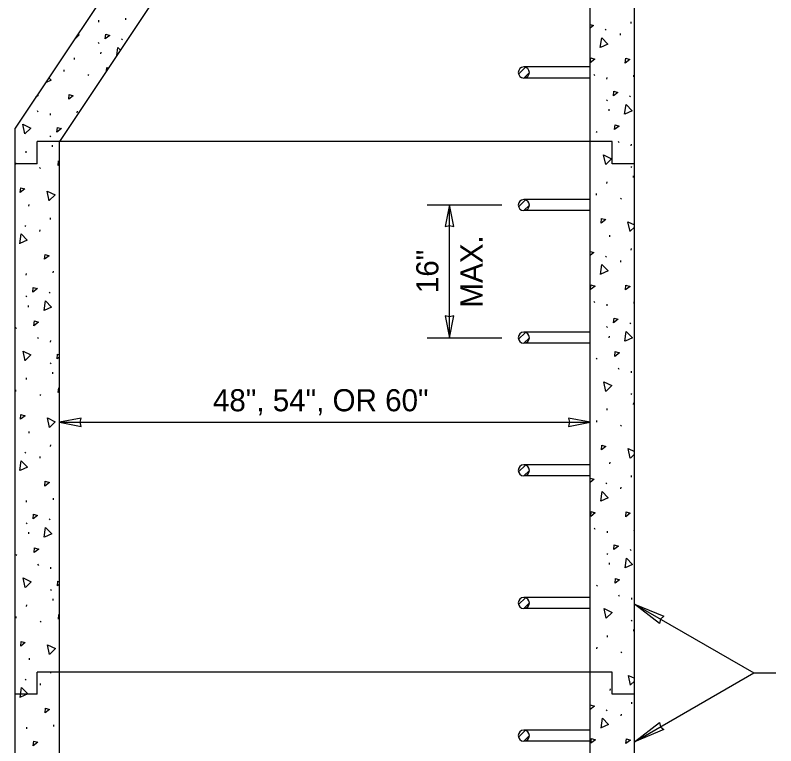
# Model space of a CAD drawing. Extents: x 99862 to 104211, y 98939 to 102076.
# Drawn here: x 100813 to 101364, y 101014 to 101543 of the extents above; entities that cross this region are included whole.
import ezdxf

# ---------------------------------------------------------------- set-up
doc = ezdxf.new("R2010")
doc.units = 0
for name, color, linetype in [('Level 15', 7, 'Continuous'), ('Level 17', 7, 'Continuous'), ('Level 18', 7, 'Continuous'), ('Level 19', 7, 'Continuous'), ('Level 20', 7, 'Continuous')]:
    doc.layers.add(name, color=color, linetype=linetype)

msp = doc.modelspace()

# ---------------------------------------------------------------- linework, layer by layer
at = {"layer": 'Level 15'}
for p, q in [((101111.39, 101406.06), (101165.22, 101406.06)), ((101127.39, 101309.84), (101127.39, 101406.06)), ((101111.39, 101309.84), (101165.22, 101309.84)), ((100845.22, 101248.56), (101229.22, 101248.56)), ((101261.22, 101116.96), (101347.53, 101067.13)), ((101261.22, 101017.3), (101347.53, 101067.13)), ((101347.53, 101067.13), (101363.53, 101067.13))]:
    msp.add_line(p, q, dxfattribs=at)
for points in [[(101127.39, 101406.06), (101124.3, 101390.33), (101127.39, 101391.06), (101130.47, 101390.33)], [(101127.39, 101309.84), (101130.47, 101325.56), (101127.39, 101324.84), (101124.3, 101325.56)], [(100845.22, 101248.56), (100860.94, 101245.48), (100860.21, 101248.56), (100860.94, 101251.64)], [(101229.22, 101248.56), (101213.49, 101251.64), (101214.22, 101248.56), (101213.49, 101245.48)], [(101261.22, 101116.96), (101282.48, 101108.13), (101280.07, 101106.07), (101279.5, 101102.96)], [(101261.22, 101017.3), (101279.5, 101031.3), (101280.07, 101028.18), (101282.48, 101026.13)]]:
    msp.add_lwpolyline(points, close=True, dxfattribs=at)
at = {"layer": 'Level 17'}
for p, q in [((101229.22, 100299.79), (101229.22, 101853.53)), ((101261.22, 100251.79), (101261.22, 101853.53)), ((101005.22, 101749.47), (100813.22, 101461.47)), ((101037.22, 101739.79), (100845.22, 101451.79)), ((100813.22, 100251.79), (100813.22, 101461.47)), ((100829.22, 101435.79), (100829.22, 101451.79)), ((100845.22, 101451.79), (100829.22, 101451.79)), ((101229.22, 101451.79), (100845.22, 101451.79)), ((100845.22, 100299.79), (100845.22, 101451.79)), ((101245.22, 101451.79), (101229.22, 101451.79)), ((101245.22, 101435.79), (101245.22, 101451.79)), ((100829.22, 101435.79), (100813.22, 101435.79)), ((101261.22, 101435.79), (101245.22, 101435.79)), ((100829.22, 101051.79), (100829.22, 101067.79)), ((100845.22, 101067.79), (100829.22, 101067.79)), ((101229.22, 101067.79), (100845.22, 101067.79)), ((101245.22, 101067.79), (101229.22, 101067.79)), ((101245.22, 101051.79), (101245.22, 101067.79)), ((100829.22, 101051.79), (100813.22, 101051.79)), ((101261.22, 101051.79), (101245.22, 101051.79))]:
    msp.add_line(p, q, dxfattribs=at)
at = {"layer": 'Level 18'}
for p, q in [((101177.38, 101500.66), (101182.36, 101505.62)), ((101229.22, 101505.79), (101181.22, 101505.79)), ((101181.21, 101497.79), (101185.21, 101501.78)), ((101229.22, 101497.79), (101181.22, 101497.79)), ((101177.38, 101404.66), (101182.36, 101409.62)), ((101181.21, 101401.79), (101185.21, 101405.78)), ((101229.22, 101409.79), (101181.22, 101409.79)), ((101229.22, 101401.79), (101181.22, 101401.79)), ((101177.38, 101308.66), (101182.36, 101313.62)), ((101229.22, 101313.79), (101181.22, 101313.79)), ((101181.21, 101305.79), (101185.21, 101309.78)), ((101229.22, 101305.79), (101181.22, 101305.79)), ((101177.38, 101212.66), (101182.36, 101217.62)), ((101181.21, 101209.79), (101185.21, 101213.78)), ((101229.22, 101217.79), (101181.22, 101217.79)), ((101229.22, 101209.79), (101181.22, 101209.79)), ((101177.38, 101116.66), (101182.36, 101121.62)), ((101229.22, 101121.79), (101181.22, 101121.79)), ((101181.21, 101113.79), (101185.21, 101117.78)), ((101229.22, 101113.79), (101181.22, 101113.79)), ((101177.38, 101020.66), (101182.36, 101025.62)), ((101181.21, 101017.79), (101185.21, 101021.78)), ((101229.22, 101025.79), (101181.22, 101025.79)), ((101229.22, 101017.79), (101181.22, 101017.79))]:
    msp.add_line(p, q, dxfattribs=at)
for centre in [(101181.21, 101501.79), (101181.21, 101405.79), (101181.21, 101309.79), (101181.21, 101213.79), (101181.21, 101117.79), (101181.21, 101021.79)]:
    msp.add_arc(centre, 4, 270, 269.93, dxfattribs=at)
at = {"layer": 'Level 19'}
for p, q in [((100873.69, 101538.35), (100873.77, 101539.57)), ((100893.19, 101540.02), (100893.28, 101541.24)), ((101258.79, 101537.34), (101258.88, 101538.56)), ((101240.18, 101533.15), (101240.9, 101532.63)), ((101251.19, 101528.77), (101251.28, 101529.99)), ((100873.33, 101523.4), (100874.05, 101522.87)), ((100890.14, 101526.16), (100890.86, 101525.63)), ((100875.24, 101515.38), (100875.33, 101516.6)), ((100856.13, 101511.19), (100856.21, 101512.41)), ((100848.53, 101502.62), (100848.62, 101503.84)), ((100865.86, 101500.46), (100866.58, 101499.93)), ((101231.78, 101500.55), (101232.28, 101499.54)), ((101260.82, 101498.67), (101260.91, 101499.89)), ((101241.33, 101497), (101241.41, 101498.22)), ((101257.78, 101484.81), (101258.5, 101484.28)), ((101240.96, 101482.05), (101241.68, 101481.52)), ((100829.12, 101474.4), (100829.62, 101473.39)), ((100838.66, 101470.84), (100838.75, 101472.07)), ((100858.16, 101472.52), (100858.25, 101473.74)), ((101242.88, 101474.03), (101242.96, 101475.25)), ((100838.3, 101455.9), (100839.02, 101455.37)), ((101233.49, 101459.11), (101234.21, 101458.58)), ((101249.38, 101452.2), (101249.88, 101451.19)), ((101258.92, 101448.65), (101259.01, 101449.87)), ((100821.1, 101443.68), (100821.19, 101444.91)), ((100840.22, 101447.88), (100840.3, 101449.1)), ((100813.51, 101435.11), (100813.59, 101436.34)), ((101258.56, 101433.7), (101259.28, 101433.17)), ((100830.83, 101432.95), (100831.55, 101432.42)), ((101241.36, 101421.49), (101241.45, 101422.71)), ((101260.48, 101425.68), (101260.56, 101426.91)), ((101233.77, 101412.92), (101233.85, 101414.14)), ((100823.14, 101405.02), (100823.22, 101406.24)), ((101251.09, 101410.76), (101251.81, 101410.23)), ((100838.7, 101395.34), (100838.79, 101396.56)), ((100820.09, 101391.15), (100820.81, 101390.62)), ((100831.1, 101386.76), (100831.19, 101387.99)), ((101243.4, 101382.82), (101243.48, 101384.04)), ((101258.96, 101373.14), (101259.05, 101374.36)), ((101240.35, 101368.95), (101241.07, 101368.42)), ((101251.36, 101364.57), (101251.45, 101365.79)), ((100821.24, 101354.99), (100821.32, 101356.22)), ((100840.74, 101356.67), (100840.82, 101357.89)), ((100820.87, 101340.05), (100821.59, 101339.52)), ((100837.69, 101342.8), (100838.41, 101342.27)), ((101231.95, 101336.35), (101232.45, 101335.34)), ((101260.99, 101334.47), (101261.08, 101335.69)), ((100822.79, 101332.03), (100822.88, 101333.25)), ((101241.5, 101332.8), (101241.58, 101334.02)), ((101241.13, 101317.85), (101241.85, 101317.32)), ((101257.95, 101320.61), (101258.67, 101320.08)), ((100813.4, 101317.1), (100814.12, 101316.57)), ((100829.29, 101310.2), (100829.79, 101309.19)), ((100838.83, 101306.64), (100838.92, 101307.87)), ((101243.05, 101309.83), (101243.13, 101311.05)), ((100838.47, 101291.7), (100839.19, 101291.17)), ((101233.66, 101294.9), (101234.38, 101294.38)), ((100840.39, 101283.68), (100840.47, 101284.9)), ((101249.55, 101288), (101250.05, 101286.99)), ((101259.09, 101284.45), (101259.18, 101285.67)), ((100821.27, 101279.48), (100821.36, 101280.71)), ((100813.68, 101270.91), (100813.76, 101272.14)), ((100831, 101268.75), (100831.72, 101268.22)), ((101258.73, 101269.5), (101259.45, 101268.97)), ((101260.65, 101261.48), (101260.73, 101262.71)), ((101241.53, 101257.29), (101241.62, 101258.51)), ((101233.94, 101248.72), (101234.02, 101249.94)), ((101251.26, 101246.56), (101251.98, 101246.03)), ((100823.31, 101240.82), (100823.39, 101242.04)), ((100838.87, 101231.14), (100838.96, 101232.36)), ((100820.26, 101226.95), (100820.98, 101226.42)), ((100831.28, 101222.56), (100831.36, 101223.79)), ((101243.57, 101218.62), (101243.65, 101219.84)), ((101259.13, 101208.94), (101259.22, 101210.16)), ((101240.52, 101204.75), (101241.24, 101204.22)), ((101251.53, 101200.37), (101251.62, 101201.59)), ((100821.41, 101190.79), (100821.49, 101192.02)), ((100840.91, 101192.47), (100840.99, 101193.69)), ((100821.04, 101175.85), (100821.76, 101175.32)), ((100837.86, 101178.6), (100838.58, 101178.07)), ((101232.12, 101172.15), (101232.62, 101171.14)), ((101241.67, 101168.6), (101241.75, 101169.82)), ((101261.16, 101170.27), (101261.22, 101171.02)), ((100822.96, 101167.83), (100823.05, 101169.05)), ((100813.57, 101152.9), (100814.29, 101152.37)), ((101241.3, 101153.65), (101242.02, 101153.12)), ((101258.12, 101156.4), (101258.84, 101155.88)), ((100829.46, 101145.99), (100829.96, 101144.98)), ((100839, 101142.44), (100839.09, 101143.67)), ((101243.22, 101145.63), (101243.3, 101146.85)), ((101233.83, 101130.7), (101234.55, 101130.17)), ((100838.64, 101127.5), (100839.36, 101126.97)), ((100840.56, 101119.48), (100840.64, 101120.7)), ((101249.72, 101123.8), (101250.22, 101122.79)), ((101259.26, 101120.25), (101259.35, 101121.47)), ((100821.44, 101115.28), (100821.53, 101116.51)), ((100813.85, 101106.71), (100813.93, 101107.94)), ((100831.17, 101104.55), (100831.89, 101104.02)), ((101258.9, 101105.3), (101259.62, 101104.77)), ((101260.82, 101097.28), (101260.9, 101098.5)), ((101241.7, 101093.09), (101241.79, 101094.31)), ((101234.11, 101084.52), (101234.19, 101085.74)), ((101251.43, 101082.36), (101252.15, 101081.83)), ((100823.48, 101076.62), (100823.56, 101077.84)), ((100839.04, 101066.93), (100839.13, 101068.16)), ((100820.43, 101062.75), (100821.15, 101062.22)), ((100831.45, 101058.36), (100831.53, 101059.59)), ((101243.74, 101054.42), (101243.82, 101055.64)), ((101259.3, 101044.74), (101259.39, 101045.96)), ((101240.69, 101040.55), (101241.41, 101040.02)), ((101251.7, 101036.17), (101251.79, 101037.39)), ((100821.58, 101026.59), (100821.66, 101027.82)), ((100841.08, 101028.27), (100841.16, 101029.49))]:
    msp.add_line(p, q, dxfattribs=at)
for points in [[(101229.22, 101536.46), (101231.74, 101535.7), (101229.22, 101533.77)], [(100858.56, 101529.49), (100859.47, 101529.05), (100855.9, 101525.5)], [(100878.39, 101526.17), (100878.73, 101529.6), (100881.7, 101528.7), (100878.39, 101526.17)], [(101236.57, 101519.88), (101237.55, 101526.98), (101242.01, 101522.39), (101236.68, 101519.92)], [(100886.68, 101513.99), (100887.52, 101519.98), (100889.39, 101518.05)], [(101229.27, 101508.88), (101229.6, 101512.31), (101232.58, 101511.41), (101229.27, 101508.88)], [(101254.58, 101508.64), (101254.92, 101512.07), (101257.89, 101511.17), (101254.58, 101508.64)], [(100879.34, 101502.97), (100879.57, 101505.31), (100880.68, 101504.98)], [(100837.6, 101498.04), (100839.35, 101496.23), (100835.07, 101494.25)], [(101246.02, 101484.82), (101246.36, 101488.25), (101249.34, 101487.35), (101246.02, 101484.82)], [(100829.22, 101485.47), (100829.92, 101485.26), (100828.2, 101483.95)], [(100851.92, 101482.48), (100852.26, 101485.91), (100855.23, 101485.01), (100851.92, 101482.48)], [(100863.85, 101479.74), (100863.86, 101479.81), (100863.89, 101479.8)], [(101254.17, 101471.53), (101255.15, 101478.63), (101259.6, 101474.04), (101254.28, 101471.57)], [(100820.19, 101457.33), (100818.69, 101464.35), (100824.45, 101461.55), (100820.29, 101457.41)], [(100843.36, 101458.66), (100843.7, 101462.1), (100846.68, 101461.2), (100843.36, 101458.66)], [(101246.87, 101460.53), (101247.2, 101463.96), (101250.18, 101463.06), (101246.87, 101460.53)], [(101240.45, 101435.14), (101238.95, 101442.15), (101244.71, 101439.35), (101240.55, 101435.21)], [(100844.21, 101434.38), (100844.54, 101437.81), (100845.22, 101437.61)], [(100845.22, 101435.15), (100844.21, 101434.38)], [(100816.89, 101414.98), (100817.23, 101418.41), (100820.2, 101417.51), (100816.89, 101414.98)], [(100837.79, 101408.98), (100836.29, 101416), (100842.04, 101413.2), (100837.89, 101409.06)], [(101237.15, 101392.79), (101237.49, 101396.22), (101240.46, 101395.31), (101237.15, 101392.79)], [(101258.05, 101386.79), (101256.55, 101393.8), (101261.22, 101391.53)], [(101261.22, 101389.92), (101258.15, 101386.86)], [(100816.48, 101377.87), (100817.47, 101384.98), (100821.92, 101380.38), (100816.6, 101377.92)], [(100834.49, 101366.63), (100834.83, 101370.06), (100837.8, 101369.16), (100834.49, 101366.63)], [(101229.22, 101372.31), (101231.91, 101371.5), (101229.22, 101369.44)], [(101236.74, 101355.68), (101237.73, 101362.78), (101242.18, 101358.19), (101236.85, 101355.72)], [(100825.93, 101342.81), (100826.27, 101346.24), (100829.25, 101345.34), (100825.93, 101342.81)], [(101229.44, 101344.68), (101229.77, 101348.11), (101232.75, 101347.21), (101229.44, 101344.68)], [(101254.75, 101344.44), (101255.09, 101347.87), (101258.06, 101346.96), (101254.75, 101344.44)], [(100834.08, 101329.53), (100835.06, 101336.63), (100839.52, 101332.03), (100834.19, 101329.57)], [(101246.19, 101320.62), (101246.53, 101324.05), (101249.51, 101323.15), (101246.19, 101320.62)], [(100826.78, 101318.53), (100827.11, 101321.96), (100830.09, 101321.06), (100826.78, 101318.53)], [(101254.34, 101307.33), (101255.32, 101314.43), (101259.77, 101309.84), (101254.45, 101307.37)], [(100820.36, 101293.13), (100818.86, 101300.15), (100824.62, 101297.35), (100820.46, 101293.21)], [(100843.53, 101294.46), (100843.87, 101297.9), (100845.22, 101297.49)], [(100845.22, 101295.75), (100843.53, 101294.46)], [(101247.04, 101296.33), (101247.37, 101299.76), (101250.35, 101298.86), (101247.04, 101296.33)], [(101240.62, 101270.93), (101239.12, 101277.95), (101244.88, 101275.15), (101240.72, 101271.01)], [(100844.38, 101270.18), (100844.71, 101273.61), (100845.22, 101273.46)], [(100845.22, 101270.82), (100844.38, 101270.18)], [(100817.06, 101250.78), (100817.4, 101254.21), (100820.37, 101253.31), (100817.06, 101250.78)], [(100837.96, 101244.78), (100836.46, 101251.8), (100842.21, 101249), (100838.06, 101244.86)], [(101237.32, 101228.58), (101237.66, 101232.02), (101240.63, 101231.11), (101237.32, 101228.58)], [(101258.22, 101222.59), (101256.72, 101229.6), (101261.22, 101227.41)], [(101261.22, 101225.55), (101258.32, 101222.66)], [(100816.65, 101213.67), (100817.64, 101220.78), (100822.09, 101216.18), (100816.77, 101213.72)], [(101229.22, 101208.16), (101232.08, 101207.3), (101229.22, 101205.11)], [(100834.66, 101202.43), (100835, 101205.86), (100837.97, 101204.96), (100834.66, 101202.43)], [(101236.91, 101191.48), (101237.9, 101198.58), (101242.35, 101193.98), (101237.03, 101191.52)], [(100826.1, 101178.61), (100826.44, 101182.04), (100829.42, 101181.14), (100826.1, 101178.61)], [(101229.61, 101180.48), (101229.94, 101183.91), (101232.92, 101183.01), (101229.61, 101180.48)], [(101254.92, 101180.24), (101255.26, 101183.67), (101258.23, 101182.76), (101254.92, 101180.24)], [(100834.25, 101165.33), (100835.23, 101172.43), (100839.69, 101167.83), (100834.36, 101165.37)], [(101246.36, 101156.42), (101246.7, 101159.85), (101249.68, 101158.95), (101246.36, 101156.42)], [(100826.95, 101154.33), (100827.28, 101157.76), (100830.26, 101156.86), (100826.95, 101154.33)], [(101254.51, 101143.13), (101255.49, 101150.23), (101259.94, 101145.64), (101254.62, 101143.17)], [(100820.53, 101128.93), (100819.03, 101135.94), (100824.79, 101133.14), (100820.63, 101129.01)], [(100843.7, 101130.26), (100844.04, 101133.7), (100845.22, 101133.34)], [(100845.22, 101131.42), (100843.7, 101130.26)], [(101247.21, 101132.13), (101247.54, 101135.56), (101250.52, 101134.66), (101247.21, 101132.13)], [(100844.55, 101105.98), (100844.88, 101109.41), (100845.22, 101109.31)], [(101240.79, 101106.73), (101239.29, 101113.75), (101245.05, 101110.95), (101240.89, 101106.81)], [(100845.22, 101106.49), (100844.55, 101105.98)], [(100817.23, 101086.58), (100817.57, 101090.01), (100820.54, 101089.11), (100817.23, 101086.58)], [(100838.13, 101080.58), (100836.63, 101087.6), (100842.38, 101084.8), (100838.23, 101080.66)], [(101258.39, 101058.39), (101256.89, 101065.4), (101261.22, 101063.29)], [(101261.22, 101061.18), (101258.49, 101058.46)], [(100816.82, 101049.47), (100817.81, 101056.58), (100822.26, 101051.98), (100816.94, 101049.52)], [(101229.22, 101043.43), (101229.27, 101044), (101232.25, 101043.1), (101229.22, 101040.78)], [(100834.83, 101038.23), (100835.17, 101041.66), (100838.14, 101040.76), (100834.83, 101038.23)], [(101237.08, 101027.28), (101238.07, 101034.38), (101242.52, 101029.78), (101237.2, 101027.32)], [(100826.27, 101014.41), (100826.61, 101017.84), (100829.59, 101016.94), (100826.27, 101014.41)], [(101229.78, 101016.28), (101230.11, 101019.71), (101233.09, 101018.81), (101229.78, 101016.28)], [(101255.09, 101016.04), (101255.43, 101019.47), (101258.4, 101018.56), (101255.09, 101016.04)]]:
    msp.add_lwpolyline(points, dxfattribs=at)

# ---------------------------------------------------------------- texts
at = {"layer": 'Level 20'}
for s, p in [('MAX.', (101151.39, 101331.6)), ('16"', (101119.39, 101342.08))]:
    msp.add_text(s, height=16, rotation=90, dxfattribs=at).set_placement(p)
msp.add_text('48", 54", OR 60"', height=16, dxfattribs=at).set_placement((100956.27, 101256.56))

doc.saveas('drawing.dxf')
